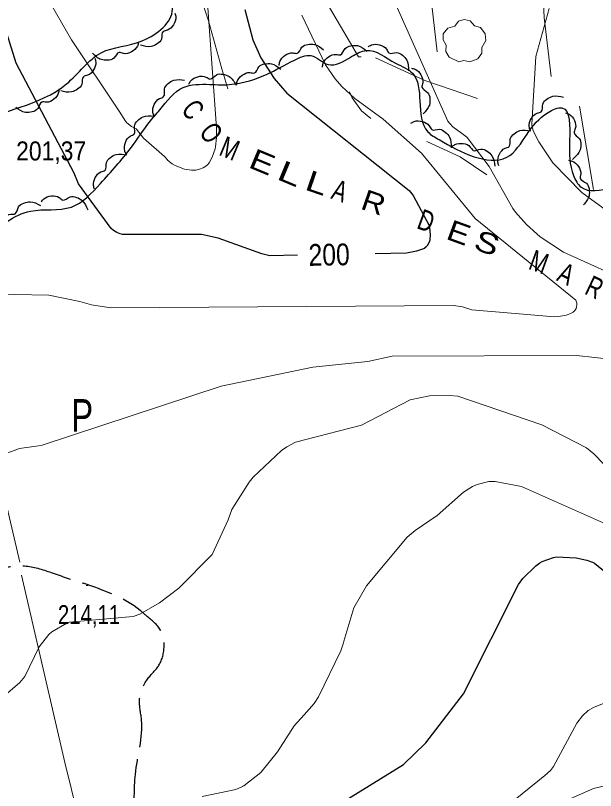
# Model space of a CAD drawing. Extents: x 480269 to 484877, y 4383588 to 4386804.
# Drawn here: x 483117.1 to 483384, y 4385730.7 to 4386087.1 of the extents above; entities that cross this region are included whole.
import ezdxf
from ezdxf.enums import TextEntityAlignment as Align

# ---------------------------------------------------------------- set-up
doc = ezdxf.new("R2010")
doc.units = 0
doc.header["$LTSCALE"] = 3.8
doc.linetypes.add('LONG_DASHED', pattern=[7.5, 6, -1.5])
for name, color, linetype, lineweight in [('27', 7, 'Continuous', 25), ('29', 7, 'Continuous', 13), ('38', 7, 'Continuous', 25), ('51', 7, 'Continuous', 13), ('7', 7, 'Continuous', 13), ('8', 7, 'Continuous', 25), ('9', 7, 'Continuous', 13)]:
    doc.layers.add(name, color=color, linetype=linetype, lineweight=lineweight)
doc.layers.add('31', color=7, linetype='Continuous')
doc.layers.add('5', color=7, linetype='Continuous')

msp = doc.modelspace()

# ---------------------------------------------------------------- linework, layer by layer
at = {"layer": '27'}
for points in [[(483064.72, 4386413.68), (483075.11, 4386426.47), (483135.83, 4386424.07), (483202.14, 4386422.47), (483237.29, 4386411.28), (483258.86, 4386407.28), (483285.23, 4386414.48), (483290.02, 4386412.08), (483280.44, 4386401.69), (483240.49, 4386387.3), (483208.53, 4386356.93), (483163.79, 4386316.16), (483146.21, 4386280.99), (483144.61, 4386248.22), (483153.4, 4386215.45), (483158.2, 4386184.28), (483172.58, 4386170.69), (483189.36, 4386151.5), (483187.76, 4386127.52), (483182.16, 4386108.34), (483189.36, 4386089.96), (483175.77, 4386075.57), (483156.6, 4386069.97), (483140.62, 4386055.59), (483097.48, 4386035.6), (483066.32, 4386003.63), (483015.98, 4385975.65), (482990.42, 4385962.87), (482978.43, 4385978.85), (482969.65, 4386002.03), (482939.29, 4386033.2), (482890.55, 4386075.57), (482870.58, 4386098.75), (482868.98, 4386106.74), (482881.76, 4386126.72), (482913.72, 4386169.09), (482939.29, 4386212.25), (482956.06, 4386255.41), (482991.22, 4386300.18), (483001.6, 4386322.56), (483017.58, 4386330.55), (483030.37, 4386352.93), (483047.94, 4386385.7), (483064.72, 4386413.68)], [(483156.21, 4386009.89), (483170.34, 4386026.39), (483178.7, 4386037.94), (483183.5, 4386043.75), (483194.27, 4386053.97), (483206.46, 4386055.39), (483216.71, 4386055.43), (483232.55, 4386060), (483245.46, 4386066.6), (483253.04, 4386068.65), (483260.92, 4386064.55), (483271.71, 4386068.18), (483278.5, 4386071), (483292.03, 4386065.15), (483299.83, 4386060.51), (483303.18, 4386047.69), (483306.85, 4386033.59), (483312, 4386029.99), (483328.14, 4386022.12), (483343.14, 4386021.87), (483352.48, 4386032.59), (483362.13, 4386042.43), (483368.54, 4386044.64), (483372.08, 4386029.75), (483373.89, 4386013.45), (483377.32, 4386008.16), (483391.52, 4386007.58), (483405.68, 4386007.9), (483414.9, 4386009.68), (483428.75, 4386020.56), (483459.76, 4386040.57), (483476.41, 4386048.65), (483492.56, 4386057.36), (483517.72, 4386067.53), (483518.92, 4386070.85), (483526.55, 4386077.76), (483531.76, 4386094.72), (483534.02, 4386115.79), (483537.23, 4386124.96), (483536.55, 4386134.27), (483532.36, 4386147.31), (483521.68, 4386156.19), (483508.43, 4386162.72), (483498.81, 4386170.94), (483489.52, 4386184.78), (483481.4, 4386189.37), (483471.95, 4386194.86)], [(483190.51, 4386088.14), (483190.89, 4386086.41), (483189.82, 4386082.77), (483187.04, 4386080.34), (483185.08, 4386079.72), (483184.25, 4386076.26), (483182.27, 4386074.02), (483179.51, 4386072.8), (483174.58, 4386073.4)], [(483173.73, 4386074.62), (483173.19, 4386072.93), (483170.44, 4386070.31), (483166.82, 4386069.6), (483164.81, 4386070.04), (483162.36, 4386067.46), (483159.53, 4386066.51), (483156.53, 4386066.83), (483152.57, 4386069.82)], [(483238.4, 4386064.15), (483238.75, 4386065.89), (483241.19, 4386068.79), (483244.71, 4386069.9), (483246.75, 4386069.69), (483248.9, 4386072.52), (483251.61, 4386073.78), (483254.63, 4386073.79), (483258.9, 4386071.26)], [(483258.39, 4386063.35), (483258.71, 4386065.09), (483261.12, 4386068.03), (483264.62, 4386069.18), (483266.67, 4386069), (483268.78, 4386071.86), (483271.47, 4386073.16), (483274.49, 4386073.21), (483278.79, 4386070.74)], [(483279.31, 4386072.67), (483280.86, 4386073.53), (483284.66, 4386073.54), (483287.78, 4386071.57), (483288.94, 4386069.87), (483292.49, 4386070.06), (483295.2, 4386068.81), (483297.16, 4386066.51), (483297.99, 4386061.62)], [(483153.67, 4386067.44), (483154.07, 4386065.71), (483153.06, 4386062.06), (483150.32, 4386059.59), (483148.37, 4386058.93), (483147.59, 4386055.46), (483145.65, 4386053.19), (483142.91, 4386051.92), (483137.98, 4386052.45)], [(483218.76, 4386054.97), (483219.09, 4386056.71), (483221.48, 4386059.65), (483224.99, 4386060.82), (483227.03, 4386060.64), (483229.14, 4386063.5), (483231.83, 4386064.8), (483234.85, 4386064.86), (483239.15, 4386062.4)], [(483299.25, 4386062.88), (483300.96, 4386062.39), (483303.65, 4386059.72), (483304.47, 4386056.12), (483304.09, 4386054.1), (483306.74, 4386051.73), (483307.78, 4386048.93), (483307.54, 4386045.91), (483304.68, 4386041.87)], [(483180.96, 4386040.72), (483180.36, 4386042.39), (483180.97, 4386046.14), (483183.43, 4386048.89), (483185.29, 4386049.76), (483185.68, 4386053.29), (483187.36, 4386055.76), (483189.95, 4386057.32), (483194.91, 4386057.34)], [(483196.86, 4386055.52), (483197.78, 4386057.04), (483201.07, 4386058.93), (483204.76, 4386058.77), (483206.61, 4386057.88), (483209.59, 4386059.81), (483212.57, 4386060.07), (483215.41, 4386059.05), (483218.56, 4386055.22)], [(483137.18, 4386053.42), (483136.97, 4386051.66), (483134.76, 4386048.58), (483131.33, 4386047.2), (483129.28, 4386047.25), (483127.36, 4386044.26), (483124.76, 4386042.79), (483121.74, 4386042.55), (483117.29, 4386044.74)], [(483353.91, 4386034.22), (483353.47, 4386035.94), (483354.4, 4386039.61), (483357.09, 4386042.14), (483359.02, 4386042.84), (483359.72, 4386046.33), (483361.61, 4386048.64), (483364.33, 4386049.97), (483369.27, 4386049.55)], [(483168.08, 4386023.26), (483167.37, 4386024.88), (483167.7, 4386028.66), (483169.94, 4386031.59), (483171.74, 4386032.59), (483171.87, 4386036.14), (483173.36, 4386038.73), (483175.82, 4386040.48), (483180.77, 4386040.86)], [(483370.22, 4386042.38), (483371.86, 4386041.72), (483374.26, 4386038.77), (483374.69, 4386035.11), (483374.1, 4386033.14), (483376.48, 4386030.5), (483377.21, 4386027.6), (483376.65, 4386024.63), (483373.37, 4386020.91)], [(483299.04, 4386037.54), (483300.6, 4386038.38), (483304.4, 4386038.34), (483307.49, 4386036.33), (483308.63, 4386034.62), (483312.18, 4386034.77), (483314.88, 4386033.49), (483316.81, 4386031.16), (483317.58, 4386026.26)], [(483339.57, 4386017.94), (483339.04, 4386019.63), (483339.8, 4386023.35), (483342.36, 4386026.01), (483344.26, 4386026.8), (483344.79, 4386030.31), (483346.56, 4386032.71), (483349.21, 4386034.17), (483354.17, 4386033.99)], [(483317.84, 4386026.72), (483319.29, 4386027.75), (483323.06, 4386028.19), (483326.38, 4386026.59), (483327.73, 4386025.03), (483331.23, 4386025.62), (483334.07, 4386024.69), (483336.28, 4386022.62), (483337.65, 4386017.86)], [(483153.52, 4386007.17), (483153.02, 4386008.87), (483153.85, 4386012.58), (483156.46, 4386015.19), (483158.37, 4386015.94), (483158.97, 4386019.45), (483160.79, 4386021.81), (483163.47, 4386023.22), (483168.42, 4386022.94)], [(483371.49, 4386020.53), (483373.23, 4386020.17), (483376.11, 4386017.7), (483377.19, 4386014.17), (483376.97, 4386012.13), (483379.78, 4386009.96), (483381.02, 4386007.24), (483381.01, 4386004.22), (483378.44, 4385999.97)], [(483231.2, 4385389.63), (483227.44, 4385405.62), (483221.8, 4385432.89), (483216.16, 4385454.52), (483213.34, 4385472.39), (483206.76, 4385488.37), (483202.06, 4385497.78), (483193.6, 4385515.64), (483186.08, 4385531.63), (483183.26, 4385543.86), (483184.2, 4385559.84), (483187.96, 4385575.83), (483188.9, 4385591.82), (483184.2, 4385605.92), (483168.22, 4385621.91), (483149.42, 4385640.72), (483137.2, 4385654.83), (483120.28, 4385667.99), (483098.66, 4385678.34), (483077.99, 4385685.86), (483072.35, 4385691.5), (483076.11, 4385715.01), (483081.75, 4385762.97), (483085.51, 4385790.24), (483086.45, 4385812.81), (483082.69, 4385831.62), (483068.59, 4385843.85), (483053.55, 4385846.67), (483034.75, 4385843.85), (483023.47, 4385846.67), (483015.01, 4385863.6), (483002.79, 4385900.27), (483004.67, 4385919.08), (483018.77, 4385934.13), (483062.95, 4385960.46), (483103.36, 4385984.91), (483124.04, 4385997.13), (483142.84, 4385999.02), (483156.21, 4386009.89)], [(483128.97, 4386001.38), (483130.12, 4386002.74), (483133.66, 4386004.11), (483137.27, 4386003.38), (483138.96, 4386002.21), (483142.21, 4386003.65), (483145.19, 4386003.45), (483147.84, 4386002), (483150.36, 4385997.73)], [(483109.83, 4385988.87), (483109.84, 4385990.65), (483111.69, 4385993.96), (483114.93, 4385995.72), (483116.98, 4385995.9), (483118.54, 4385999.09), (483120.96, 4386000.85), (483123.93, 4386001.44), (483128.6, 4385999.77)], [(482599.89, 4385643.3), (482628.86, 4385671.49), (482714.99, 4385745.13), (482794.85, 4385810.14), (482867.67, 4385855.58), (482941.27, 4385895.53), (482964.76, 4385912.76), (482973.37, 4385911.19), (482981.98, 4385879.86), (482998.42, 4385827.38), (483006.25, 4385814.84), (483025.83, 4385810.93), (483050.88, 4385818.76), (483058.71, 4385808.58), (483056.36, 4385779.59), (483052.45, 4385741.21), (483034.44, 4385691.86), (483035.22, 4385677.76), (483043.84, 4385669.93), (483091.6, 4385655.04), (483126.05, 4385633.11), (483147.97, 4385609.61), (483156.58, 4385589.25), (483155.8, 4385568.88), (483155.02, 4385552.43), (483155.02, 4385532.85), (483155.02, 4385519.53), (483152.67, 4385510.13)]]:
    msp.add_spline(points, degree=3, dxfattribs=at)
at = {"layer": '29'}
msp.add_lwpolyline([(483321.12, 4386065.83), (483316.58, 4386067.95), (483315.17, 4386070.49), (483315.27, 4386073.47), (483313.9, 4386075.88), (483313.94, 4386078.63), (483316.1, 4386081.23), (483319.29, 4386082.23), (483320.94, 4386084.42), (483323.51, 4386085.25), (483326.37, 4386084.6), (483328.32, 4386082.33), (483331.13, 4386081.51), (483333.26, 4386078.66), (483333.5, 4386075.53), (483331.62, 4386072.38), (483331.62, 4386069.7), (483329.8, 4386067.09), (483326.18, 4386065.75), (483323.41, 4386066.38)], close=True, dxfattribs=at)
at = {"layer": '38', "linetype": 'LONG_DASHED'}
for points in [[(483222.84, 4385328.78), (483233.49, 4385331.65), (483248.44, 4385336.61), (483252.54, 4385340.94), (483258.88, 4385354.18), (483261.76, 4385364.09), (483264.07, 4385370.4), (483271.55, 4385381.16), (483280.42, 4385394.23), (483287.47, 4385408.23), (483295.91, 4385425.29), (483304.52, 4385439.96), (483308.91, 4385446.59), (483318.63, 4385460.51), (483325.16, 4385473.38), (483329.03, 4385484.99), (483336.9, 4385500.43), (483342.08, 4385509.3), (483351.29, 4385526.25), (483356.88, 4385535.07), (483367.82, 4385552.46), (483372.61, 4385560.56), (483384.55, 4385574.31), (483394.22, 4385589.19), (483401.11, 4385600.15), (483408.96, 4385613.82), (483416.11, 4385628.46), (483421.62, 4385644.25), (483425.26, 4385652.82), (483437.44, 4385668.5), (483447.61, 4385682.66), (483455.49, 4385695.61), (483457.94, 4385709.1), (483457.8, 4385712.22), (483460.32, 4385716.64), (483471.95, 4385728.32), (483483.41, 4385737.85), (483491.91, 4385744.84), (483502.88, 4385754.26), (483511.53, 4385762), (483517.86, 4385770.14), (483520.82, 4385773.68), (483521.2, 4385789.84), (483522.3, 4385808.2), (483521.83, 4385825.17), (483522.61, 4385837.11), (483524.33, 4385844.04), (483529.61, 4385862.88), (483530.12, 4385879.57), (483529.5, 4385895.4), (483531.44, 4385911.89), (483533.11, 4385922.24), (483534.94, 4385934.41), (483535.75, 4385947.11), (483535.49, 4385954.95), (483538.08, 4385971.48), (483542.8, 4385983), (483551.34, 4385997.49), (483555.36, 4386004.16), (483555.47, 4386004.25)], [(483065.16, 4385830), (483073.47, 4385835), (483086.82, 4385835.33), (483098.05, 4385834.25), (483112.5, 4385833.54), (483121.28, 4385834), (483133.49, 4385830.95), (483148.28, 4385826.01)], [(483269.19, 4385377.79), (483265.83, 4385379.76), (483259.03, 4385384.12), (483248.33, 4385390.08), (483241.93, 4385401.56), (483240.31, 4385411.32), (483239.53, 4385423.1), (483237.61, 4385429.2), (483228.77, 4385444.16), (483215.59, 4385471.64), (483211.39, 4385484.05), (483206.78, 4385496.53), (483203.95, 4385506.6), (483198.79, 4385527.78), (483197.64, 4385533.81), (483194.47, 4385554.66), (483187.12, 4385575.33), (483180.81, 4385599.81), (483178.92, 4385612.27), (483174.66, 4385634.07), (483172.09, 4385649.52), (483170.18, 4385665.56), (483170.94, 4385687.86), (483170.82, 4385701.87), (483170.52, 4385716.56), (483170.83, 4385718.14), (483172.28, 4385738.14), (483175.1, 4385763.48), (483174.2, 4385772.45), (483177.9, 4385781.99), (483183.14, 4385788.4), (483185.49, 4385797.11), (483184.14, 4385804.05), (483177.92, 4385810.59), (483174.55, 4385813.49), (483148.28, 4385826.01)]]:
    msp.add_spline(points, degree=3, dxfattribs=at)
at = {"layer": '51'}
msp.add_line((483383.06, 4386007.1), (483376.63, 4386045.41), dxfattribs=at)
for points in [[(483005.34, 4386336.41), (483017.51, 4386281.19), (483027.52, 4386237.22), (483029.38, 4386226.52), (483035.96, 4386200.84), (483043.48, 4386169.57), (483052.02, 4386129.85), (483061.86, 4386081.96), (483073.72, 4386029.62), (483084.77, 4385982.18), (483119.1, 4385835.67)], [(483175.66, 4386210.77), (483180.32, 4386193.71), (483185.78, 4386170.2), (483189.3, 4386147.31), (483194.4, 4386124.33), (483199.7, 4386103.5), (483206, 4386084.56), (483212.01, 4386062.5), (483214.82, 4386053.42)], [(483311.06, 4386070.38), (483308.68, 4386091.88), (483305.49, 4386125.02), (483305.06, 4386132.38)], [(483244.39, 4386120.59), (483254.59, 4386102.8), (483266.69, 4386082.16), (483274.96, 4386068.09), (483276.11, 4386068.12)], [(483363.65, 4386058.97), (483360.41, 4386086.13), (483359.67, 4386098.69)], [(483282.77, 4386067.64), (483305.51, 4386057.12), (483329.63, 4386048.99)], [(483280.67, 4386039.73), (483276.39, 4386043.32), (483272.08, 4386049.21), (483270.77, 4386051.99)], [(483334.01, 4386013.83), (483321.66, 4386022.06), (483306.35, 4386029.22)], [(483240.31, 4385333.5), (483213.63, 4385444.02), (483179.14, 4385584.7), (483139.77, 4385743.55), (483119.86, 4385829.82)], [(483518.19, 4385778.58), (483483.09, 4385760.05), (483458.37, 4385749.62), (483427.91, 4385742.41), (483383.06, 4385731.68), (483341.78, 4385713.39), (483311.74, 4385700.46), (483292.21, 4385692.99)]]:
    msp.add_lwpolyline(points, dxfattribs=at)
at = {"layer": '7'}
msp.add_line((483149.63, 4385824.97), (483150.63, 4385824.97), dxfattribs=at)
at = {"layer": '8'}
for points in [[(483222.67, 4386089.9), (483226.3, 4386075.85), (483229.98, 4386067.59), (483236.18, 4386058.05), (483241.98, 4386051.43), (483298.24, 4386006.56), (483300.05, 4386004.33), (483307.45, 4385990.59), (483307.68, 4385989.55), (483307.96, 4385986.22), (483307.74, 4385984.12), (483307.75, 4385983.98), (483307.75, 4385983.85), (483307.59, 4385983.31), (483306.96, 4385981.9), (483306.6, 4385981.32), (483306.38, 4385981.03), (483305.92, 4385980.56), (483305.37, 4385980.1), (483305.24, 4385980.02), (483301.67, 4385978.69), (483297.05, 4385977.81), (483282.59, 4385977.53)], [(483246.84, 4385976.85), (483234.09, 4385976.61), (483230.42, 4385977.46), (483210.35, 4385984.76), (483202.75, 4385986.37), (483166.32, 4385986.41), (483165.25, 4385986.65), (483163.71, 4385987.28), (483162.23, 4385988.2), (483161.11, 4385989.18), (483146.09, 4386009.64), (483144.06, 4386014.61), (483117.41, 4386065.18), (483111.56, 4386083.89), (483110.63, 4386085.63), (483109.11, 4386087.74)], [(483250.64, 4385715.03), (483295.58, 4385742.7), (483305.99, 4385752.7), (483323.25, 4385775.13), (483348.56, 4385825.5), (483350.51, 4385828.17), (483356.49, 4385834.06), (483358.41, 4385835.46), (483359.39, 4385836.01), (483364.6, 4385837.83), (483366.06, 4385838.14), (483375.01, 4385837.68), (483379.97, 4385836.66), (483382.57, 4385835.68), (483383.44, 4385835.26), (483403.75, 4385818.74)]]:
    msp.add_lwpolyline(points, dxfattribs=at)
at = {"layer": '9'}
for points in [[(483199.58, 4386173.45), (483209.66, 4386035.47), (483209.63, 4386030.94), (483209.19, 4386026.76), (483208.99, 4386025.84), (483207.6, 4386021.87), (483206.29, 4386019.3), (483205.53, 4386018.37), (483204.31, 4386017.48), (483203.51, 4386017.03), (483201.8, 4386016.4), (483200.13, 4386016.03), (483198.04, 4386015.95), (483194.81, 4386016.48), (483190.53, 4386018.12), (483189.19, 4386018.85), (483187.13, 4386020.63), (483187.11, 4386020.66), (483187.11, 4386020.67), (483187.1, 4386020.7), (483185.68, 4386022.21), (483175.98, 4386030.7), (483172.87, 4386034.89), (483172.77, 4386035), (483172.65, 4386035.03), (483171.55, 4386035.42), (483170.53, 4386036.02), (483168.4, 4386037.68), (483167.72, 4386038.44), (483164.79, 4386043.07), (483142.9, 4386075.82), (483122.27, 4386111.91)], [(483287.71, 4386102.18), (483316.11, 4386038.43), (483316.89, 4386037.42), (483318.41, 4386035.92), (483323.96, 4386031.76), (483324.96, 4386030.92), (483335.07, 4386017.65), (483346, 4385998.33), (483347.22, 4385996.63), (483352.16, 4385990.97), (483358.58, 4385985.24), (483369.19, 4385978.29), (483388.24, 4385969.66)], [(483404.99, 4385985.8), (483377.72, 4386005.7), (483364.28, 4386019.32), (483357.86, 4386028.96), (483355.49, 4386033.79), (483354.9, 4386035.75), (483354.68, 4386037.04), (483356.46, 4386068.19), (483362.66, 4386090.34)], [(483248.8, 4386087.3), (483259.7, 4386064.39), (483264.19, 4386057.98), (483267.31, 4386054.5), (483273.26, 4386048.99), (483286.3, 4386039.4)], [(483286.3, 4386039.4), (483303.85, 4386023.74), (483328.59, 4385993.72), (483374.86, 4385956.19), (483375.21, 4385955.25), (483375.32, 4385954.79), (483375.38, 4385954.05), (483375.27, 4385953.2), (483375.04, 4385952.41), (483374.77, 4385951.83), (483374.58, 4385951.55), (483374.18, 4385951.08), (483373.71, 4385950.67), (483373.42, 4385950.47), (483372.24, 4385949.88), (483370.51, 4385949.28), (483367.94, 4385948.79), (483365.08, 4385948.59), (483327.12, 4385951.79), (483322.81, 4385953.05), (483318.65, 4385953.68), (483160.92, 4385952.59), (483152.08, 4385953.98), (483146.75, 4385955.65), (483132.4, 4385958.43), (483100.79, 4385959.09)], [(483400.59, 4385928.06), (483375.29, 4385930.78), (483290.45, 4385930.45), (483279.23, 4385927.99), (483253.92, 4385925.33), (483211.73, 4385916.71), (483128.87, 4385889.32), (483126.7, 4385889.09), (483119.04, 4385887.93), (483111.17, 4385885.12)], [(483102.26, 4385766.03), (483119.2, 4385780.43), (483121.4, 4385783.18), (483127.99, 4385796.85), (483132.51, 4385802.53), (483133.89, 4385803.7), (483140.81, 4385807.69), (483141.89, 4385808.13), (483171.27, 4385810.74), (483174.37, 4385811.86), (483183.34, 4385817.07), (483192.24, 4385823.81), (483207.66, 4385839.28), (483214.92, 4385855.14), (483216.72, 4385859.99), (483224.71, 4385872.53), (483226.46, 4385874.79), (483239.58, 4385887.12), (483241.9, 4385888.8), (483245.89, 4385890.89), (483276.28, 4385898.69), (483298.73, 4385910.38), (483307.54, 4385912.18), (483316.8, 4385912.41), (483320.62, 4385912.03), (483359.33, 4385898.85), (483379.81, 4385888.32), (483383.14, 4385885.6), (483396.95, 4385871.26)], [(483389.92, 4385852.81), (483349.93, 4385870.58), (483337.84, 4385872.81), (483334.93, 4385872.82), (483329.61, 4385871.48), (483327.43, 4385870.47), (483323.28, 4385867.99), (483311.19, 4385857.14), (483300.98, 4385850.36), (483297.29, 4385847.23), (483278.55, 4385824.82), (483272.75, 4385814.7), (483268.14, 4385799.44), (483268.12, 4385799.19), (483268, 4385798.6), (483266.8, 4385795.01), (483256.61, 4385773.79), (483254.54, 4385770.7), (483249.95, 4385765.49), (483245.4, 4385760.47), (483237.67, 4385748.5), (483229.98, 4385738.95), (483222.16, 4385732.83), (483221.89, 4385732.72), (483221.82, 4385732.71), (483221.8, 4385732.7), (483221.8, 4385732.66), (483221.61, 4385732.52), (483218.44, 4385731.15), (483202.94, 4385727.92)], [(483315.79, 4385701.38), (483360.64, 4385737.64), (483360.65, 4385737.64), (483363.24, 4385740.01), (483364.65, 4385741.79), (483375.32, 4385761.73), (483377.98, 4385765), (483380.65, 4385767.46), (483383.05, 4385768.93), (483387.27, 4385770.6), (483391.66, 4385771.75), (483391.71, 4385771.71), (483399.56, 4385772.41), (483408.32, 4385771.97), (483417.3, 4385770.17), (483434.25, 4385764.59), (483461.02, 4385764.71), (483470.22, 4385767.8), (483474.68, 4385770.07), (483484.17, 4385777.01)]]:
    msp.add_lwpolyline(points, dxfattribs=at)

# ---------------------------------------------------------------- texts
at = {"layer": '31', "width": 0.75}
msp.add_text('P', height=15, dxfattribs=at).set_placement((483147.82, 4385895.69), align=Align.CENTER)
at = {"layer": '5'}
for s, rotation, width, p in [('C', 308.259, 0.75, (483195.1, 4386040.91)), ('O', 308.259, 0.75, (483203.52, 4386030.23)), ('M', 337.386, 0.75, (483213.89, 4386021.57)), ('E', 337.386, 1.3, (483228.86, 4386015.33)), ('L', 337.386, 1.5, (483241.65, 4386010.01)), ('L', 340.988, 1.4, (483254.35, 4386005.61)), ('A', 340.988, 0.75, (483264.83, 4386001.99)), ('R', 340.988, 1.15, (483280.39, 4385996.63)), ('D', 340.009, 0.75, (483304.47, 4385988.23)), ('E', 340.009, 1.2, (483319.49, 4385982.76)), ('S', 340.009, 1.3, (483332.47, 4385978.04)), ('M', 340.009, 0.75, (483356.37, 4385969.34)), ('A', 334.685, 0.75, (483368.48, 4385964.02)), ('R', 334.685, 0.75, (483381.55, 4385957.84))]:
    msp.add_text(s, height=9.49, rotation=rotation, dxfattribs=dict(at, width=width)).set_placement(p, align=Align.CENTER)
at = {"layer": '7'}
for s, width, p in [('201,37', 0.9, (483117.43, 4386020.43)), ('214,11', 0.8, (483136.65, 4385807.23))]:
    msp.add_text(s, height=8.75, dxfattribs=dict(at, width=width)).set_placement(p)
at = {"layer": '8', "width": 0.85}
msp.add_text('200', height=10, rotation=1.1, dxfattribs=at).set_placement((483261.52, 4385972.12), align=Align.CENTER)

doc.saveas('drawing.dxf')
